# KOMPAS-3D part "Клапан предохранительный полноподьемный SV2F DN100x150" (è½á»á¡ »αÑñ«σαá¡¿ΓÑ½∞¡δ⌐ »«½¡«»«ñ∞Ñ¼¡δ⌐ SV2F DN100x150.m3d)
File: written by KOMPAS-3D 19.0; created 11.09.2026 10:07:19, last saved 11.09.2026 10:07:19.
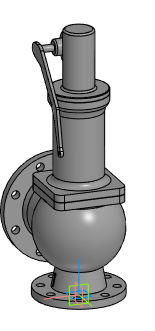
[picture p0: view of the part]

Document properties: Автор: Энергия; Полное имя файла: Z:\3.Личные\sachek\Dendor\_3D для проектировщиков\5.9 SV2F. Клапан предохранительный полноподьемный\SV2F_STP\Клапан предохранительный полноподьемный SV2F DN100x150.m3d

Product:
- Part/product: Клапан предохранительный полноподьемный SV2F DN100x150

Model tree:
1. Операция без истории:1  (labels: Клапан предохранительный полноподьемный SV2F DN100x150)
